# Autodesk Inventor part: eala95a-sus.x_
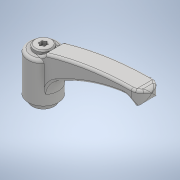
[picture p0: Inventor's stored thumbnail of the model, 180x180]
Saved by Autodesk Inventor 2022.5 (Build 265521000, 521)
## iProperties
Created: 2018-05
Part Number: eala95a-sus.x_
Material: 一般
Document SubType Name: Modeling
Designer: imaocorp
Density: 1 g/cm^3
Appearance: 既定
Sending System: SOLIDWORKS 2016-2016286
MC: AMD64
MC_MODEL: AMD64 Family 21 Model 2 Stepping 0, AuthenticAMD
OS: Windows_NT
FRU: Parasolid Version 28.0, build 224,  7-29-2016
FORMAT: text
GUISE: transmit
KEY: eala95a-sus
FILE: eala95a-sus.x_t
DATE: Fri May 18 11:32:47 2018
Author: imaocorp
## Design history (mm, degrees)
feature "Base1"
node "ソリッド1"
